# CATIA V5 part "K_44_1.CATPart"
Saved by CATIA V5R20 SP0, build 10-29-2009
Part number: 44_1
Bounding box of the stored display mesh (mm): x -30 to 30, y -50 to 50, z -160 to 160
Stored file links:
  G:\Khaled_CFAO_2011\ST2M\ST2M_GR1\mponsin\Khaled\CAD_ThinkMOTION\K_44_1.CATPart
  C:\Users\Socar\Documents\thinkmotion\Final\Diff2.CATProduct
  G:\Khaled_CFAO_2011\ST2M\ST2M_GR1\mponsin\Khaled\CAD_ThinkMOTION\K_mponsin.CATProduct
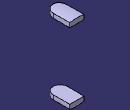
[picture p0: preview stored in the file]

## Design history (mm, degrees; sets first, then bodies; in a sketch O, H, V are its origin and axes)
External parameters (linked from other documents)
  `External.R appui` = 30 mm
  External.Lappui = 50 mm
  External.Lmeplat = 25 mm
  External.Rmeplat = 5 mm
  `External.R interne` = 160 mm
Set1
  Plane1: linked copy from another document
  Plane2 "interface 11/V": linked copy from another document
  DatumPoint1: linked copy from another document
  Plane3: linked copy from another document
  Line1 "axe general": linked copy from another document
Body1 (main body)
  Sketch1 on Plane1, origin (0, 0, 138.9213), H (1, 0, 0), V (0, -1, 0)
    line L1 (-30, -50) -> (30, -50)
    line L2 (30, -50) -> (30, 20)
    line L3 (-30, 20) -> (-30, -50)
    reference intersected line E1 through (0, -50) direction (1, 0) from Plane2
    axis line L4 (-30, 20) -> (30, 20)
    arc A1 centre (0, 20) radius 30 from (30, 20) to (-30, 20) ccw
    point P5 (0, 20)
    distance L3 V = 30 {= `External.R appui`}
    distance A1 H = 50 {= External.Lappui}
    horizontal: L1 H, L4 H
    vertical: L2 V, L3 V
    symmetry: L2 L3 V
    coincidence: L1 E1
    midpoint: P5 L4
    tangency: A1 L2
  Pad1: profile Sketch1, direction (0, 0, 1), up to Plane3
  Sketch2 on face of Pad1 from Sketch1.L1, origin (0, 50, 0), H (-1, 0, 0), V (0, 0, 1)
    circle A1 centre (0, 0) radius 160
    circle A2 centre (0, 0) radius 200
    radius A1 = 160 {= `External.R interne`}
    distance A1 A2 = 40
  Pocket1: profile Sketch2, direction (0, -1, 0), through (limit type 3)
  CircPattern1: of the body so far, instances 2, angular step 180, axis from Line1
